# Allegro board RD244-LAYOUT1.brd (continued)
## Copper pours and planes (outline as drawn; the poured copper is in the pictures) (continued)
LGND on CONDUCTIVE3: 246.44,18.81 246.14,19.2 245.6,19.74 245.55,19.82 245.53,19.92 245.53,35.06 240.87,39.71 240.82,39.79 240.8,39.89 240.8,50.24 234.18,56.85 234.13,56.93 234.11,57.03 234.11,73.06 234.04,73.55 234.04,73.65 234.11,74.14 234.11,118.42 234.04,118.91 234.04,118.95 234.14,119.15 234.36,119.19 234.58,119.15 234.68,118.95 234.68,118.91 234.61,118.42 234.61,74.14 234.68,73.65 234.68,73.55 234.61,73.06 234.61,57.13 241.23,50.52 241.28,50.44 241.3,50.34 241.3,39.99 245.96,35.34 246.01,35.26 246.03,35.16 246.03,20.02 246.5,19.56 246.89,19.26 246.95,19.21 246.98,19.14 246.99,19.06 246.98,18.98 246.94,18.9 246.86,18.84 246.81,18.77 246.74,18.72 246.59,18.71 246.46,18.78
LGND on CONDUCTIVE3: 261.44,70.26 260.95,70.33 259.92,70.33 259.82,70.35 259.74,70.41 254.63,75.52 249.2,75.52 249.17,75.51 249.13,75.51 241.13,75.51 241.04,75.53 240.96,75.58 240.39,76.15 240.34,76.23 240.32,76.32 240.32,80.43 240.34,80.52 240.39,80.6 241.95,82.16 242.03,82.21 242.12,82.23 249.37,82.23 249.46,82.21 249.54,82.16 250.42,81.28 250.47,81.2 250.49,81.11 250.49,80.1 250.47,80.01 250.42,79.93 250.33,79.84 250.25,79.79 250.16,79.77 249.66,79.77 249.38,79.49 249.38,76.43 249.79,76.02 254.73,76.02 254.83,76 254.91,75.95 260.02,70.83 260.95,70.83 261.44,70.91 261.54,70.91 262.03,70.83 262.35,70.83 263.2,71.68 263.2,73.7 262.8,74.1 261.61,74.1 261.43,74.17 261.36,74.35 261.36,76.56 261.36,76.6 261.37,76.64 261.37,80.97 261.44,81.15 261.62,81.22 269.49,81.22 269.67,81.15 269.74,80.97 269.74,80.02 269.67,79.84 269.49,79.77 268.97,79.77 267.92,78.72 267.92,74.35 267.85,74.17 267.67,74.1 264.1,74.1 263.7,73.7 263.7,71.58 263.68,71.48 263.63,71.4 262.63,70.41 262.55,70.35 262.45,70.33 262.03,70.33 261.54,70.26
LGND on CONDUCTIVE3: 259.39,118.83 258.12,118.83 258.02,118.85 257.94,118.9 254.61,122.24 243.8,122.24 243.76,122.25 243.73,122.27 239.73,126.27 239.71,126.3 239.7,126.34 239.7,129.81 239.71,129.85 239.73,129.88 239.97,130.12 240,130.14 240.04,130.15 241.26,130.15 241.3,130.14 241.33,130.12 242.48,128.97 248.43,128.97 248.47,128.96 248.5,128.94 249.04,128.4 249.06,128.37 249.07,128.33 249.07,127.04 249.06,127 249.04,126.97 248.96,126.89 248.93,126.87 248.89,126.86 248.51,126.86 247.9,126.25 247.9,124.09 249.25,122.74 254.77,122.74 254.81,122.73 254.84,122.71 258.22,119.33 259.39,119.33 260.02,119.42 260.13,119.38 260.47,119.33 260.54,119.33 261.6,120.39 261.6,123.68 261.6,123.72 261.61,123.75 261.61,128.09 261.68,128.27 261.86,128.34 269.73,128.34 269.91,128.27 269.98,128.09 269.98,127.13 269.91,126.95 269.73,126.88 269.21,126.88 268.16,125.83 268.16,121.81 268.09,121.63 267.91,121.56 262.57,121.56 262.1,121.08 262.1,120.29 262.08,120.19 262.03,120.11 260.82,118.9 260.74,118.85 260.64,118.83 260.47,118.83 259.98,118.76
LGND on CONDUCTIVE4: outline of 150 points within 248.3,18.8 298.45,143.8 ; 25 cut-outs
LGND on CONDUCTIVE5: outline of 224 points within 235.06,1.55 298.45,143.8 ; 46 cut-outs
OUTA2 on TOP: 245.01,6.25 244.9,6.29 244.86,6.4 244.86,7.19 244.9,7.33 245.04,7.37 245.58,7.25 246.05,7.72 245.93,8.26 246.02,8.44 246.21,8.37 246.22,8.33 246.52,6.99 246.71,6.8 246.79,6.8 247.17,6.91 247.23,6.92 247.28,6.9 247.35,6.83 247.36,6.73 247.34,6.69 247.3,6.65 247.32,6.64 247.34,6.61 247.36,6.58 247.34,6.44 247.21,6.38 247.17,6.39 246.79,6.5 246.5,6.5 246.29,6.29 246.25,6.26 246.19,6.25
OUTA2 on BOTTOM: 247.15,6.47 247.14,6.57 247.16,6.61 247.2,6.65 247.18,6.66 247.16,6.69 247.14,6.72 247.16,6.86 247.29,6.92 247.33,6.91 247.71,6.8 251.71,6.8 254.29,9.38 254.34,9.41 254.4,9.43 258.54,9.43 258.84,9.47 258.88,9.47 259.64,9.47 259.84,9.28 259.64,9.07 258.88,9.07 258.84,9.08 258.54,9.12 254.46,9.12 251.88,6.54 251.83,6.51 251.78,6.5 247.71,6.5 247.33,6.39 247.27,6.38 247.22,6.4
OUTB2 on TOP: 251.34,5.63 251.45,6.01 251.45,7.49 251.11,7.83 250.91,7.83 249.97,7.22 249.77,7.26 249.81,7.47 250.28,7.77 250.28,8.43 249.81,8.73 249.77,8.94 249.97,8.98 251.13,8.23 251.74,7.61 251.75,7.55 251.75,6.01 251.86,5.63 251.87,5.56 251.84,5.5 251.76,5.44 251.65,5.45 251.62,5.47 251.6,5.5 251.59,5.48 251.56,5.46 251.53,5.44 251.39,5.46 251.33,5.59
OUTB2 on BOTTOM: 251.53,5.35 251.51,5.48 251.52,5.52 251.55,5.55 251.52,5.58 251.51,5.62 251.53,5.75 251.65,5.82 251.68,5.81 251.71,5.8 251.89,5.73 254.89,8.73 254.94,8.76 255,8.78 258.54,8.78 258.84,8.82 258.88,8.82 259.64,8.82 259.84,8.62 259.64,8.43 258.88,8.43 258.84,8.43 258.54,8.47 255.06,8.47 252.03,5.44 252.01,5.42 251.98,5.41 251.71,5.3 251.68,5.29 251.65,5.28
OUTD2 on TOP: 250.46,2.01 250.26,2.06 250.3,2.26 250.77,2.57 250.77,2.7 250.05,2.7 249.9,2.85 250.05,3 250.77,3 250.77,3.23 250.3,3.54 250.26,3.74 250.46,3.79 251.62,3.05 251.82,3.11 251.87,3.12 251.91,3.11 251.97,3.08 252.01,3.02 252.01,3 252.05,2.91 252.02,2.82 252,2.79 251.98,2.63 251.82,2.59 251.51,2.68
OUTD2 on BOTTOM: 244.57,1.48 244.35,1.7 244.57,1.93 244.75,1.93 244.8,1.92 245.13,1.85 250.69,1.85 251.47,2.63 251.66,2.98 251.83,3.05 251.94,2.91 251.94,2.89 251.96,2.89 252.1,2.78 252.03,2.61 251.68,2.42 250.86,1.59 250.81,1.56 250.75,1.55 245.13,1.55 244.8,1.48 244.75,1.48
OUTE on CONDUCTIVE4: 250.7,50.65 245.7,50.65 245.6,50.67 245.52,50.72 237.02,59.22 236.97,59.3 236.95,59.4 236.95,119.93 236.97,120.03 237.02,120.11 238.68,121.77 238.76,121.82 238.86,121.84 253.07,121.84 253.17,121.82 253.25,121.77 256.97,118.05 258.85,118.05 259.34,118.12 259.38,118.12 259.58,118.02 259.62,117.8 259.58,117.58 259.38,117.48 259.34,117.48 258.85,117.55 256.86,117.55 256.77,117.57 256.69,117.62 252.97,121.34 238.96,121.34 237.45,119.83 237.45,76.65 237.65,76.45 238.18,76.45 238.21,76.46 238.25,76.46 241.49,76.46 241.59,76.44 241.67,76.39 243.32,74.73 253.52,74.73 253.62,74.71 253.7,74.66 258.76,69.59 260.82,69.59 261.31,69.66 261.35,69.66 261.55,69.56 261.59,69.34 261.55,69.12 261.35,69.02 261.31,69.02 260.82,69.09 258.66,69.09 258.56,69.11 258.48,69.16 253.42,74.23 243.22,74.23 243.12,74.25 243.04,74.3 241.39,75.96 238.73,75.96 238.7,75.95 238.66,75.95 237.65,75.95 237.45,75.75 237.45,59.5 245.8,51.15 250.8,51.15 250.9,51.13 250.98,51.08 254.26,47.8 254.31,47.72 254.33,47.62 254.18,47.39 253.9,47.44
OUTF on TOP: 260.78,14.46 260.79,14.51 260.9,14.89 260.9,16.37 260.91,16.43 261.17,16.71 261.22,16.74 261.28,16.75 261.38,16.75 262.81,17.61 263.1,17.65 263.9,17.65 264.95,16.6 263.9,15.55 263.1,15.55 262.91,15.57 262.54,15.71 261.8,16.18 261.38,16.18 261.2,16 261.2,14.89 261.31,14.51 261.32,14.43 261.28,14.36 261.21,14.32 261.13,14.32 261.09,14.34 261.05,14.38 261.04,14.36 261.01,14.34 260.98,14.32 260.86,14.33 260.79,14.42
OUTF on BOTTOM: 259.75,120.08 259.69,120.09 259.65,120.12 259.61,120.16 259.58,120.2 259.57,120.26 259.57,120.57 259.58,120.63 259.61,120.67 259.8,120.86 259.85,120.89 259.91,120.91 261.49,120.91 261.9,120.49 261.49,120.08
OUTF on CONDUCTIVE3: 250.6,50.85 245.4,50.85 245.3,50.87 245.22,50.92 237.12,59.02 237.07,59.1 237.05,59.2 237.05,122.5 237.07,122.6 237.12,122.68 238.12,123.68 238.2,123.73 238.3,123.75 238.88,123.75 239.37,123.82 239.41,123.82 239.61,123.72 239.65,123.5 239.61,123.28 239.41,123.18 239.37,123.18 238.88,123.25 238.4,123.25 237.55,122.4 237.55,77.9 237.8,77.65 237.85,77.65 237.88,77.64 238.29,77.64 238.78,77.71 238.82,77.71 239.02,77.61 239.06,77.39 239.02,77.17 238.82,77.07 238.78,77.07 238.29,77.14 237.8,77.14 237.55,76.89 237.55,59.3 245.5,51.35 250.7,51.35 250.8,51.33 250.88,51.28 254.44,47.72 254.49,47.64 254.51,47.54 254.36,47.31 254.08,47.36
OUTF on CONDUCTIVE4: 261.3,71.7 260.81,71.77 258.3,71.77 258.2,71.79 258.12,71.84 254.57,75.4 244.22,75.4 244.12,75.42 244.04,75.47 242.38,77.14 239.37,77.14 238.88,77.07 238.84,77.07 238.64,77.17 238.6,77.39 238.64,77.61 238.84,77.71 238.88,77.71 239.37,77.64 242.48,77.64 242.58,77.62 242.66,77.57 244.32,75.9 254.67,75.9 254.77,75.88 254.85,75.83 258.4,72.27 260.81,72.27 261.3,72.34 261.34,72.34 261.54,72.24 261.58,72.02 261.54,71.8 261.34,71.7
PFC_OFF on BOTTOM: 119.07,11.75 118.96,11.79 118.92,11.9 118.92,12.05 118.96,12.16 119.07,12.2 119.78,12.2 120.31,12.73 120.35,12.76 120.41,12.78 121.44,12.78 121.74,12.82 121.78,12.82 122.47,12.82 122.67,12.62 122.47,12.43 121.78,12.43 121.74,12.43 121.44,12.47 121.05,12.47 120.69,12.12 120.36,11.79 120.32,11.76 120.26,11.75
PN on BOTTOM (solid shape): 186.3,32.27 186.57,32.47 186.8,32.23 186.8,32.18 186.66,31.48 188.48,29.66 189.18,29.8 189.47,29.6 189.27,29.3 185.97,28.68 185.75,28.75 185.68,28.97
PN on BOTTOM (solid shape): 117.65,124.25 118.12,124.58 118.59,124.25 119.17,122.67 119.12,122.21 118.71,122 118.42,122.09 118.24,122.32 118.21,122.39 118.03,122.39 118,122.32 117.36,122.03 117.06,122.67
PN on CONDUCTIVE3 (solid shape): 112.42,98.34 112.58,98.48 112.72,98.33 112.72,98.31 112.69,98.07 113.41,97.35 113.65,97.38 113.81,97.25 113.68,97.08 112.43,96.92 112.3,96.96 112.26,97.09
PN on TOP: 209.16,15.06 209.05,15.1 209.01,15.21 209.01,17.56 209.05,17.67 209.16,17.71 209.42,17.71 209.48,17.7 209.52,17.67 210.67,16.52 210.7,16.48 210.71,16.42 210.71,15.21 210.67,15.1 210.56,15.06
PN on TOP: 188.35,6.48 188.35,6.72 187.88,6.96 187.83,6.99 187.79,7.04 187.77,7.3 187.99,7.43 188.05,7.42 188.11,7.4 189.2,6.85 195.86,6.85 197.3,8.29 197.3,8.53 197.16,8.99 195.1,8.99 194.64,9.45 195.1,9.91 197.33,9.91 197.47,10.15 197.83,10.53 197.88,10.56 197.94,10.57 202.04,10.57 202.1,10.56 202.15,10.53 203.51,9.16 207.15,9.16 208.07,10.08 208.26,10.43 208.43,10.5 208.54,10.36 208.54,10.34 208.56,10.34 208.7,10.23 208.63,10.06 208.28,9.87 207.32,8.9 207.27,8.87 207.21,8.86 203.45,8.86 203.39,8.87 203.34,8.9 201.98,10.27 198,10.27 197.83,10.1 197.83,9.97 197.87,9.91 200.1,9.91 200.56,9.45 200.1,8.99 198.04,8.99 197.85,8.35 197.85,8.24 197.83,8.14 197.78,8.06 196.14,6.42 196.06,6.37 195.96,6.35 189.2,6.35 188.11,5.8 188.07,5.78 187.76,5.92 187.88,6.24
PN on TOP: 125.17,10.5 125.18,10.55 125.25,10.88 125.25,10.94 125.15,11.03 124.62,11.03 124.6,11.04 124.55,11.03 124.51,11.04 124.2,11.14 123.89,11.04 123.84,11.03 123.71,11.11 123.71,11.26 123.75,11.3 123.71,11.34 123.71,11.49 123.84,11.57 123.89,11.56 124.2,11.46 124.51,11.56 124.55,11.57 124.6,11.56 124.64,11.57 124.68,11.56 125.06,11.45 125.75,11.45 125.8,11.49 125.86,11.5 127.47,11.5 127.57,11.46 127.62,11.35 127.62,11.14 127.53,10.86 127.26,10.74 127.03,10.74 126.96,10.75 126.9,10.76 126.43,10.95 125.78,10.95 125.58,10.75 125.62,10.55 125.62,10.5 125.62,10.32 125.4,10.1 125.17,10.32
PN on TOP: 226.36,2.15 226.2,2.15 225.9,2.1 225.87,2.1 225.7,2.1 225.5,2.3 225.7,2.5 225.87,2.5 225.9,2.5 226.14,2.46 226.33,2.46 226.68,2.57 227.02,2.75 227.07,2.77 227.1,2.77 227.49,2.77 227.81,2.84 227.9,2.85 228.12,2.62 227.9,2.4 227.81,2.41 227.49,2.48 227.19,2.48 227.03,2.18 226.98,2.12 226.9,2.1 226.88,2.1 226.86,2.08 226.84,2.07 226.78,2.04 226.71,2.05
PN on TOP: 215.67,2.54 215.56,2.58 215.52,2.69 215.52,5.04 215.53,5.1 215.77,5.36 215.82,5.39 215.88,5.4 218.72,5.4 219.05,5.47 219.1,5.47 219.28,5.47 219.5,5.25 219.28,5.03 219.1,5.03 219.05,5.03 218.72,5.1 215.94,5.1 215.82,4.98 215.82,3.88 215.95,3.75 217.69,3.75 217.75,3.74 217.79,3.71 217.95,3.55 219.15,3.55 219.26,3.51 219.3,3.4 219.3,3.3 219.26,3.19 219.15,3.15 216.59,3.15 216.02,2.58 215.98,2.55 215.92,2.54
PN on TOP: 199.31,2.85 199.25,2.86 199.21,2.89 198.84,3.26 198.81,3.3 198.8,3.36 198.8,7.95 198.84,8.06 198.95,8.1 206.85,8.1 206.96,8.06 207,7.95 207,4.86 206.99,4.8 206.96,4.76 205.09,2.89 205.05,2.86 204.99,2.85
PN on TOP: 100.19,1.51 100.13,1.52 100.09,1.55 99.77,1.87 99.74,1.91 99.73,1.97 99.73,2.75 99.74,2.81 99.77,2.85 100.07,3.15 100.11,3.18 100.17,3.19 101.31,3.19 101.37,3.18 101.41,3.15 101.51,3.05 102.7,3.05 102.76,3.04 102.8,3.01 103.41,2.4 108.59,2.4 108.65,2.39 108.69,2.36 108.9,2.15 109.32,2.15 109.33,2.17 109.35,2.19 109.5,2.35 109.5,3.12 109.7,3.33 109.9,3.12 109.9,2.38 109.89,2.32 109.86,2.27 109.75,2.16 109.75,1.7 109.71,1.59 109.6,1.55 108.26,1.55 108.2,1.56 108.16,1.59 107.8,1.95 103.03,1.95 102.63,1.55 102.59,1.52 102.53,1.51
PN on TOP, BOTTOM: 189.13,144.72 189.07,144.73 189.03,144.76 188.48,145.31 188.45,145.35 188.44,145.41 188.44,146.86 188.45,146.92 188.48,146.96 188.84,147.32 188.88,147.35 188.94,147.36 190.11,147.36 190.17,147.35 190.21,147.32 190.57,146.96 190.6,146.92 190.61,146.86 190.61,145.18 190.6,145.12 190.57,145.08 190.25,144.76 190.21,144.73 190.15,144.72
PN on BOTTOM: 122.14,121.08 122.03,121.12 121.99,121.23 121.99,143.68 122.03,143.79 122.14,143.83 138.83,143.83 138.94,143.79 138.98,143.68 138.98,121.23 138.94,121.12 138.83,121.08
PN on BOTTOM: 120.06,24.6 120,24.61 119.96,24.64 119.14,25.46 119.11,25.5 119.1,25.56 119.1,29.34 119.11,29.4 119.14,29.44 119.96,30.26 120,30.29 120.06,30.3 124.04,30.3 124.1,30.29 124.14,30.26 124.96,29.44 124.99,29.4 125,29.34 125,25.56 124.99,25.5 124.96,25.46 124.14,24.64 124.1,24.61 124.04,24.6
PN on BOTTOM: 118.17,5.08 118.18,5.13 118.25,5.45 118.18,5.77 118.17,5.82 118.17,6.18 118.18,6.21 118.18,6.4 118.13,6.45 118.06,6.45 117.68,6.34 117.61,6.33 117.55,6.36 117.5,6.41 117.49,6.48 117.5,6.55 117.55,6.6 117.51,6.63 117.49,6.67 117.49,6.76 117.56,6.85 117.68,6.86 118.06,6.75 118.11,6.75 118.17,6.81 118.17,7.28 118.18,7.33 118.25,7.65 118.18,7.97 118.17,8.02 118.17,8.2 118.4,8.43 118.62,8.2 118.62,8.02 118.62,7.97 118.55,7.65 118.62,7.33 118.62,7.28 118.62,6.92 118.55,6.58 118.55,6.55 118.62,6.23 118.62,6.18 118.62,5.82 118.62,5.77 118.55,5.45 118.62,5.13 118.62,5.08 118.62,4.9 118.4,4.67 118.17,4.9
PN on BOTTOM: 122.23,99.96 122.17,99.97 122.13,100 120.05,102.08 120.02,102.12 120.01,102.18 120.01,104.48 120.02,104.54 120.05,104.58 121.45,105.98 121.49,106.01 121.55,106.02 137.15,106.02 137.21,106.01 137.25,105.98 138.95,104.28 138.98,104.24 138.99,104.18 138.99,101.92 138.98,101.86 138.95,101.82 137.13,100 137.09,99.97 137.03,99.96
PN on BOTTOM: 118.11,10.9 118.05,10.91 118.01,10.94 117.95,11 113.16,11 113.1,11.01 113.06,11.04 112.94,11.16 112.91,11.2 112.9,11.26 112.9,13.34 112.91,13.4 112.94,13.44 113.16,13.66 113.2,13.69 113.26,13.7 114.94,13.7 115,13.69 115.04,13.66 115.16,13.54 115.19,13.5 115.2,13.44 115.2,12.2 115.4,12 117.94,12 118,11.99 118.04,11.96 118.65,11.35 120.44,11.35 120.57,11.48 120.62,11.51 120.68,11.53 123.62,11.53 123.66,11.56 123.7,11.59 123.76,11.6 124.75,11.6 124.86,11.56 124.9,11.45 124.9,11.16 124.89,11.1 124.86,11.06 124.84,11.04 124.8,11.01 124.74,11 123.66,11 123.6,11.01 123.56,11.04 123.48,11.12 123.45,11.14 123.43,11.17 123.18,11.13 123.15,11.12 121.91,11.12 121.88,11.13 121.58,11.18 121.48,11.18 121.42,11.13 121.36,11.12 121.27,11.12 121.09,10.94 121.05,10.91 120.99,10.9
PN on BOTTOM: 124.95,4.55 124.84,4.59 124.8,4.7 124.8,6.1 124.84,6.21 124.95,6.25 127.6,6.25 127.71,6.21 127.75,6.1 127.75,4.7 127.71,4.59 127.6,4.55
PN on BOTTOM: 187.36,28.66 187.3,28.67 187.26,28.7 186.03,29.93 186,29.97 185.99,30.03 185.99,33.32 186,33.38 186.03,33.42 187.05,34.44 187.09,34.47 187.15,34.48 190.43,34.48 190.49,34.47 190.53,34.44 191.55,33.42 191.58,33.38 191.59,33.32 191.59,29.76 191.58,29.7 191.55,29.66 190.59,28.7 190.55,28.67 190.49,28.66
PN on BOTTOM: 154.02,10.7 153.97,10.71 153.92,10.74 153.11,11.56 153.07,11.6 153.06,11.66 153.06,15.44 153.07,15.5 153.11,15.54 153.92,16.36 153.97,16.39 154.02,16.4 158,16.4 158.06,16.39 158.11,16.36 158.92,15.54 158.95,15.5 158.96,15.44 158.96,11.66 158.95,11.6 158.92,11.56 158.11,10.74 158.06,10.71 158,10.7
PN on BOTTOM: 207.72,9.28 207.5,9.5 207.72,9.72 207.89,9.72 207.94,9.72 208.2,9.66 208.35,9.81 208.35,9.84 208.24,10.22 208.24,10.32 208.3,10.39 208.34,10.41 208.39,10.41 208.39,10.42 208.45,10.54 208.58,10.56 208.96,10.45 210.84,10.45 210.95,10.48 210.95,11.3 210.99,11.41 211.1,11.45 212.54,11.45 212.6,11.44 212.64,11.41 212.75,11.3 214.5,11.3 214.7,11.5 214.7,12.65 214.74,12.76 214.85,12.8 217.35,12.8 217.46,12.76 217.5,12.65 217.5,12.5 217.46,12.39 217.35,12.35 215.6,12.35 215.2,11.95 215.2,11.36 215.19,11.3 215.16,11.26 214.79,10.89 214.75,10.86 214.69,10.85 213.05,10.85 212.55,10.35 212.55,10 212.51,9.89 212.4,9.85 211.21,9.85 211.15,9.86 211.11,9.89 211,10 210.84,10.04 208.71,10.04 208.65,9.84 208.65,9.75 208.64,9.69 208.36,9.39 208.32,9.37 208.28,9.35 207.94,9.28 207.89,9.28
PN on BOTTOM: 101.71,18.86 101.23,19.42 100.22,19.97 99.15,18.9 99.15,17.35 98.9,17.1 98.65,17.35 98.65,19 98.67,19.1 98.72,19.18 99.97,20.43 100.05,20.48 100.15,20.5 101.4,21.17 101.73,21.08 101.66,20.75 101.64,20.73 101.1,20.44 101.1,20.06 101.25,19.97 101.38,19.96 101.48,19.89 101.55,19.81 101.64,19.77 101.66,19.75 101.74,19.67 101.77,19.56 101.85,19.46 101.95,19.46 102.32,19.89 102.66,19.93 102.71,19.59 102.7,19.56 102.44,19.26 102.44,18.84 104.18,17.1 104.18,16.75 103.82,16.75
PN on BOTTOM: 187.16,5.47 187.1,5.48 187.06,5.51 186.64,5.93 186.61,5.97 186.6,6.03 186.6,7.08 186.61,7.14 186.64,7.18 187.15,7.69 187.19,7.72 187.25,7.73 188.15,7.73 188.21,7.72 188.25,7.69 188.71,7.23 188.74,7.19 188.75,7.13 188.75,6.03 188.74,5.97 188.71,5.93 188.29,5.51 188.25,5.48 188.19,5.47
PN on BOTTOM: 200.55,1.82 200.49,1.83 200.45,1.86 199.26,3.05 199.23,3.09 199.22,3.15 199.22,3.31 199.23,3.37 199.26,3.41 199.29,3.44 199.33,3.47 199.39,3.48 199.57,3.48 199.63,3.47 199.67,3.44 200.76,2.35 200.79,2.31 200.8,2.25 200.8,1.97 200.76,1.86 200.65,1.82
PN on BOTTOM: 218.1,5.38 218.11,5.43 218.18,5.75 218.18,6.04 218.13,6.34 218.12,6.38 218.12,6.88 218.02,6.98 217.97,7.12 217.97,7.83 217.98,7.87 217.99,7.91 218.1,8.29 218.1,10.09 218.06,10.22 218.06,10.26 218.06,10.3 218.06,10.34 218.06,10.38 218.17,10.75 218.11,11.06 218.1,11.11 218.1,11.2 218.32,11.43 218.55,11.2 218.55,11.11 218.54,11.06 218.48,10.75 218.59,10.38 218.59,10.34 218.59,10.3 218.59,10.26 218.59,10.22 218.47,9.84 218.47,8.04 218.51,7.91 218.52,7.87 218.53,7.83 218.53,6.38 218.52,6.34 218.47,6.04 218.47,5.75 218.54,5.43 218.55,5.38 218.55,5.2 218.32,4.97 218.1,5.2
PN on BOTTOM: 119.09,100.5 117.77,101.82 117.66,101.99 117.62,102.18 117.62,120.39 117.06,121.89 117.06,121.9 117.37,122.53 118,122.24 118.12,121.92 118.24,122.24 118.87,122.53 119.18,121.9 119.17,121.89 118.62,120.39 118.62,102.39 119.94,101.06 120.05,100.9 120.09,100.71 120.09,93.54 119.59,93.04 119.09,93.54
PN on BOTTOM: 71.71,130.1 71.65,130.11 71.61,130.14 71.09,130.66 71.06,130.7 71.05,130.76 71.05,133.24 71.06,133.3 71.09,133.34 71.61,133.86 71.65,133.89 71.71,133.9 74.29,133.9 74.35,133.89 74.39,133.86 74.91,133.34 74.94,133.3 74.95,133.24 74.95,130.56 74.94,130.5 74.91,130.46 74.59,130.14 74.55,130.11 74.49,130.1
PN on CONDUCTIVE2, CONDUCTIVE5: outline of 271 points within 70.95,0.8 229.5,148.28 ; 18 cut-outs
PN on CONDUCTIVE2, CONDUCTIVE5: 116.13,3.77 116.11,3.8 116.1,3.84 116.1,17.72 116.11,17.76 116.13,17.79 119.19,20.85 119.22,20.87 119.26,20.88 130.4,20.88 130.44,20.87 130.47,20.85 133.57,17.75 133.59,17.72 133.6,17.68 133.6,9.12 133.56,9.04 133.48,9.02 132.63,8.34 133.48,7.66 133.56,7.64 133.6,7.56 133.6,4.44 133.59,4.4 133.57,4.37 131.83,2.63 131.8,2.61 131.76,2.6 117.34,2.6 117.3,2.61 117.27,2.63 ; 4 cut-outs
PN on CONDUCTIVE4: 113.28,12.9 113.24,12.91 113.21,12.93 113.09,13.05 113.07,13.08 113.06,13.12 113.06,13.65 113.07,13.69 113.09,13.72 114.55,15.18 114.58,15.2 114.62,15.21 115,15.21 115.07,15.18 115.1,15.11 115.1,13.44 114.97,13.06 114.6,12.9
PN on CONDUCTIVE4: 155.55,3.27 155.36,3.31 155.2,3.42 145.95,12.67 145.84,12.83 145.8,13.02 145.8,18.86 141.11,23.55 120.08,23.55 119.89,23.59 119.73,23.7 117.51,25.92 117.4,26.08 117.36,26.27 117.36,92.61 117.4,92.8 117.51,92.96 119.24,94.69 119.78,94.8 120.09,94.34 120.09,93.54 119.94,93.19 119.59,93.04 119,93.04 118.36,92.4 118.36,26.48 120.29,24.55 141.32,24.55 141.51,24.51 141.67,24.4 146.65,19.42 146.76,19.26 146.8,19.07 146.8,13.23 155.76,4.27 191.91,4.27 194.2,6.55 194.36,6.66 194.55,6.7 198.49,6.7 199.15,7.35 199.69,7.46 200,7 200,6.2 199.85,5.85 199.5,5.7 194.76,5.7 192.47,3.42 192.31,3.31 192.12,3.27
SIG1 on CONDUCTIVE3 (solid shape): 24.73,71.29 25.07,71.21 24.99,70.86 24.67,70.67 24.67,69.37 24.99,69.18 25.07,68.83 24.73,68.75 22.99,69.81 22.87,70.02 22.99,70.23
SIG1 on TOP: 9.56,30.46 9.5,30.48 9.46,30.51 1.4,38.56 0.86,39.37 0.67,40.33 0.67,63.89 0.86,64.85 1.4,65.66 16.27,80.53 16.27,88.5 16.28,88.55 16.32,88.6 24.42,96.71 24.47,96.74 24.53,96.75 45.72,96.75 45.78,96.74 45.83,96.71 47.77,94.77 47.83,94.71 47.86,94.66 47.87,94.6 47.87,91.59 47.86,91.54 47.82,91.49 47.38,91.04 47.33,91.01 47.27,91 44.53,91 44.47,91.01 44.42,91.04 43.71,91.75 26.54,91.75 21.46,86.67 21.46,78.71 21.45,78.65 21.42,78.6 5.67,62.85 5.67,50.13 6,49.8 6.59,49.8 9.06,52.28 9.44,54.29 9.46,54.34 9.48,54.36 9.5,54.39 9.66,54.4 9.74,54.26 9.73,54.23 9.6,53.5 10.5,52.6 11.23,52.73 11.26,52.74 11.4,52.66 11.39,52.5 11.36,52.48 11.34,52.46 11.29,52.44 9.28,52.06 5.67,48.46 5.67,41.37 12.89,34.14 12.92,34.1 12.94,34.04 12.94,32.06 12.92,32 12.89,31.96 11.44,30.51 11.4,30.48 11.34,30.46
SIG1 on TOP, CONDUCTIVE2, CONDUCTIVE5: 23.51,60.6 23.45,60.61 23.41,60.64 22.34,61.71 22.31,61.75 22.3,61.81 22.3,69.89 22.31,69.95 22.34,69.99 24.15,71.8 24.15,82.24 24.16,82.3 24.19,82.34 30.81,88.96 30.85,88.99 30.91,89 41.94,89 42,88.99 42.04,88.96 43.2,87.8 54.63,87.8 57.7,90.87 57.7,93.84 57.71,93.9 57.74,93.94 59.11,95.31 59.15,95.34 59.21,95.35 61.78,95.35 61.84,95.34 61.88,95.31 63.01,94.18 63.04,94.14 63.05,94.08 63.05,88.56 63.04,88.5 63.01,88.46 57.09,82.54 57.05,82.51 56.99,82.5 40.86,82.5 40.8,82.51 40.76,82.54 39.6,83.7 33.2,83.7 29.84,80.34 29.84,61.86 29.83,61.8 29.8,61.76 28.68,60.64 28.64,60.61 28.58,60.6
SIG1 on BOTTOM: 27.61,53.12 27.36,53.37 27.61,53.62 30.45,53.62 30.75,53.91 30.75,54.2 30.7,54.21 30.07,54.39 27.61,54.39 27.36,54.64 27.61,54.89 30.07,54.89 30.76,55.08 30.82,55.09 32,55.09 32.43,54.75 32.22,54.25 31.65,53.93 30.9,53.19 30.82,53.13 30.73,53.12
SIG1 on BOTTOM: 18,52.91 17.57,53.25 17.78,53.75 18.35,54.07 19.1,54.81 19.18,54.87 19.27,54.88 22.39,54.88 22.64,54.63 22.39,54.38 19.38,54.38 19.15,54.16 19.15,53.94 19.3,53.79 19.93,53.61 22.39,53.61 22.64,53.36 22.39,53.11 19.93,53.11 19.24,52.92 19.18,52.91
SIG1 on BOTTOM: 3.17,47.55 1.4,48.28 0.67,50.05 0.67,63.89 0.86,64.85 1.4,65.66 16.46,80.72 16.46,87.71 16.65,88.67 17.19,89.48 23.73,96.02 27.27,96.02 27.27,92.48 21.46,86.67 21.46,79.68 21.27,78.72 20.73,77.91 5.67,62.85 5.67,52.12 5.67,52.11 8.34,50.3 13.75,50.3 14.26,50.81 14.34,50.87 14.44,50.89 16.07,50.89 16.76,51.08 16.82,51.09 18,51.09 18.45,50.64 18,50.19 16.82,50.19 16.76,50.19 16.7,50.21 16.07,50.39 14.54,50.39 14.03,49.87 13.95,49.82 13.85,49.8 8.34,49.8 5.67,47.99 5,47.66 4.26,47.55
SIG1 on BOTTOM: 31.55,57.69 31.56,57.75 31.75,58.44 31.75,58.64 29.79,60.6 23.51,60.6 23.45,60.61 23.41,60.64 22.34,61.71 22.31,61.75 22.3,61.81 22.3,69.89 22.31,69.95 22.34,69.99 24.15,71.8 24.15,82.24 24.16,82.3 24.19,82.34 30.81,88.96 30.85,88.99 30.91,89 41.94,89 42,88.99 42.04,88.96 43.2,87.8 54.63,87.8 57.7,90.87 57.7,93.84 57.71,93.9 57.74,93.94 59.11,95.31 59.15,95.34 59.21,95.35 61.78,95.35 61.84,95.34 61.88,95.31 63.01,94.18 63.04,94.14 63.05,94.08 63.05,88.56 63.04,88.5 63.01,88.46 57.09,82.54 57.05,82.51 56.99,82.5 40.86,82.5 40.8,82.51 40.76,82.54 39.6,83.7 33.2,83.7 29.84,80.34 29.84,61.25 32.18,58.92 32.23,58.84 32.25,58.74 32.25,58.44 32.44,57.75 32.45,57.69 32.45,57.36 32,56.91 31.55,57.36
SIG1 on CONDUCTIVE2, CONDUCTIVE5: 9.56,30.46 9.5,30.48 9.46,30.51 1.4,38.56 0.86,39.37 0.67,40.33 0.67,63.89 0.86,64.85 1.4,65.66 16.27,80.53 16.27,88.5 16.28,88.55 16.32,88.6 24.42,96.71 24.47,96.74 24.53,96.75 45.72,96.75 45.78,96.74 45.83,96.71 47.83,94.71 47.86,94.66 47.87,94.6 47.87,91.59 47.86,91.54 47.82,91.49 47.38,91.04 47.33,91.01 47.27,91 44.53,91 44.47,91.01 44.42,91.04 43.71,91.75 26.54,91.75 21.46,86.67 21.46,78.71 21.45,78.65 21.42,78.6 5.67,62.85 5.67,41.37 12.89,34.14 12.92,34.1 12.94,34.04 12.94,32.06 12.92,32 12.89,31.96 11.44,30.51 11.4,30.48 11.34,30.46
SIG0012 on BOTTOM: 100.16,12.5 99.9,12.5 99.8,12.52 99.72,12.57 98.72,13.57 98.67,13.65 98.65,13.75 98.65,15.25 98.9,15.5 99.15,15.25 99.15,13.85 100,13 100.16,13 101.4,13.67 101.45,13.69 101.51,13.7 101.55,13.73 101.6,13.76 102.96,14.16 103.75,14.95 103.75,15.9 103.79,16.01 103.9,16.05 104.09,16.05 104.15,16.04 104.19,16.01 104.45,15.75 106.47,15.75 106.72,15.5 106.47,15.25 104.75,15.25 103.31,13.81 102.91,12.45 102.9,12.44 102.59,12.28 102.43,12.59 102.6,13.18 102.33,13.45 101.74,13.28 101.69,13.27 101.64,13.23 101.1,12.94 101.1,12.56 101.64,12.27 101.66,12.25 101.73,11.92 101.4,11.83
SIG0013 on TOP: 165.47,81.78 165.41,81.79 165.37,81.82 164.39,82.8 164.36,82.84 164.35,82.9 164.35,83.89 158.44,89.8 156.32,89.8 156.26,89.81 156.22,89.84 154.06,92 154.03,92.05 154.01,92.11 154.01,104.85 154.03,104.91 154.06,104.96 154.66,105.56 154.7,105.59 154.76,105.6 163.04,105.6 163.1,105.59 163.14,105.56 163.96,104.74 163.99,104.7 164,104.64 164,97.66 169.08,92.58 169.11,92.54 169.12,92.48 169.12,83.19 169.11,83.13 169.08,83.09 167.81,81.82 167.77,81.79 167.71,81.78
SIG0013 on TOP: 67.29,8.94 67.08,9.27 67,9.65 67,17.5 68,18.5 69,17.5 69,10.06 70.57,8.49 79.67,8.49 80.8,9.62 80.8,23.57 80.81,23.63 80.84,23.67 88.01,30.84 88.01,34.76 78.86,43.91 78.78,43.95 78.16,43.95 78.1,43.96 78.06,43.99 77.44,44.61 77.41,44.65 77.4,44.71 77.4,49.44 77.41,49.5 77.44,49.54 78.16,50.26 78.2,50.29 78.26,50.3 81.94,50.3 82,50.29 82.04,50.26 82.32,49.98 82.35,49.93 82.37,49.87 82.37,47.47 82.37,47.47 94.06,35.78 99.46,35.78 99.52,35.77 99.56,35.74 100.61,34.69 100.64,34.65 100.65,34.59 100.65,32.17 100.64,32.11 100.61,32.07 99.27,30.73 99.23,30.7 99.17,30.69 94.93,30.69 86.12,21.88 86.12,11.98 86.11,11.92 86.08,11.88 85.58,11.38 85.54,11.35 85.48,11.34 83.5,11.34 82.9,10.74 82.9,9.31 82.82,8.93 82.61,8.6 80.79,6.78 80.46,6.57 80.08,6.49 70.16,6.49 69.78,6.57 69.45,6.78
SIG0013 on TOP, BOTTOM: 74.47,11.02 74.09,11.1 73.77,11.31 73.03,12.05 72.82,12.37 72.74,12.75 72.74,18.36 67.42,23.68 58.59,23.68 55.8,20.88 55.47,20.67 55.09,20.59 42,20.59 38.21,16.79 38.03,16.65 37.82,16.55 36.92,16.69 36.5,17.5 36.52,17.7 36.58,17.88 36.67,18.06 36.79,18.21 40.88,22.3 41.21,22.51 41.59,22.59 54.68,22.59 58.16,26.07 58.71,27.08 58.71,27.64 58.79,28.02 59.01,28.35 59.75,29.09 60.07,29.3 60.45,29.38 69.43,29.38 69.81,29.3 70.13,29.09 77.57,21.65 77.78,21.33 77.86,20.95 77.86,12.17 77.78,11.79 77.57,11.47 77.41,11.31 77.09,11.1 76.71,11.02
SIG0013 on TOP, BOTTOM: 122.26,80.5 122.2,80.51 122.16,80.54 120.74,81.96 120.71,82 120.7,82.06 120.7,87.84 120.71,87.9 120.74,87.94 122.36,89.56 122.4,89.59 122.46,89.6 130.9,89.6 141.5,100.2 141.5,104.04 141.51,104.1 141.54,104.14 142.96,105.56 143,105.59 143.06,105.6 150.74,105.6 150.8,105.59 150.84,105.56 151.46,104.94 151.49,104.9 151.5,104.84 151.5,100.76 151.49,100.7 151.46,100.66 131.34,80.54 131.3,80.51 131.24,80.5
SIG0013 on BOTTOM: 44.59,25.56 44.53,25.57 44.49,25.6 43.81,26.28 43.77,26.33 43.76,26.39 43.76,28.58 43.77,28.61 43.78,28.65 43.98,28.97 55.08,40.12 55.89,40.66 56.85,40.85 72.87,40.85 72.93,40.84 72.98,40.81 75.39,38.39 80.63,38.39 86.19,43.95 86.19,57.91 86.2,57.97 86.23,58.01 103.26,75.04 103.26,78.85 95.4,86.71 95.22,86.9 94.92,87.33 94.7,87.8 94.57,88.31 94.52,88.83 94.52,111.56 84.08,122 72.34,122 72.28,122.01 72.24,122.04 71.1,123.18 71.09,123.2 71.07,123.23 71.06,123.26 71.05,123.3 71.05,125.78 71.05,125.81 71.06,125.83 71.06,126.27 71.07,126.33 71.1,126.37 72.19,127.46 72.23,127.49 72.29,127.5 85.82,127.5 86.97,127.27 87.95,126.62 99.64,114.93 100.29,113.95 100.52,112.8 100.52,90.07 108.38,82.21 109.03,81.24 109.26,80.09 109.26,73.81 109.04,72.66 108.38,71.68 92.19,55.49 92.19,42.71 91.96,41.56 91.31,40.59 81.27,30.54 81.22,30.51 81.16,30.5 76.28,30.5 76.22,30.51 76.17,30.54 70.86,35.85 57.89,35.85 47.69,25.66 47.62,25.59 47.57,25.57 47.52,25.56
SIG0013 on BOTTOM: outline of 101 points within 67,6.49 160.2,70.66
SIG0013 on BOTTOM: 94.89,3.1 94.29,3.7 94.89,4.3 95.21,4.3 95.36,4.28 95.49,4.23 95.75,4.1 98.35,4.1 98.61,4.23 98.74,4.28 98.89,4.3 99.21,4.3 99.81,3.7 99.21,3.1 98.89,3.1 98.74,3.12 98.61,3.17 97.89,3.55 96.21,3.55 95.49,3.17 95.36,3.12 95.21,3.1
SIG0013 on BOTTOM: 77.95,44.27 77.89,44.28 77.85,44.31 77.01,45.15 76.98,45.19 76.97,45.25 76.97,66.25 77.2,67.4 77.85,68.37 84.52,75.04 84.52,107.04 77.56,114 72.83,114 72.77,114.01 72.73,114.04 71.08,115.69 71.05,115.73 71.04,115.79 71.04,118.27 71.05,118.33 71.08,118.37 72.17,119.46 72.21,119.49 72.27,119.5 79.3,119.5 79.56,119.49 80.08,119.4 80.57,119.22 81.02,118.96 81.42,118.62 89.64,110.4 89.82,110.21 90.12,109.78 90.34,109.31 90.47,108.8 90.52,108.28 90.52,73.8 90.29,72.65 89.64,71.68 82.97,65.01 82.97,45.26 82.96,45.2 82.93,45.16 82.08,44.31 82.04,44.28 81.98,44.27
SIG0013 on CONDUCTIVE2, CONDUCTIVE5: 74.47,11.02 74.09,11.1 73.77,11.31 73.03,12.05 72.82,12.37 72.74,12.75 72.74,18.36 67.42,23.68 60.5,23.68 60.12,23.75 59.8,23.97 59.01,24.76 58.79,25.08 58.71,25.47 58.71,27.64 58.79,28.02 59.01,28.35 59.75,29.09 60.07,29.3 60.45,29.38 69.43,29.38 69.81,29.3 70.13,29.09 77.57,21.65 77.78,21.33 77.86,20.95 77.86,12.17 77.78,11.79 77.57,11.47 77.41,11.31 77.09,11.1 76.71,11.02
SIG0013 on CONDUCTIVE2, CONDUCTIVE5: 81.61,11.34 81.57,11.35 81.54,11.37 80.83,12.08 80.81,12.11 80.8,12.15 80.8,23.57 80.81,23.63 80.84,23.67 88.01,30.84 88.01,34.76 78.86,43.91 78.78,43.95 78.16,43.95 78.1,43.96 78.06,43.99 77.44,44.61 77.41,44.65 77.4,44.71 77.4,49.44 77.41,49.5 77.44,49.54 78.16,50.26 78.2,50.29 78.26,50.3 81.94,50.3 82,50.29 82.04,50.26 82.32,49.98 82.35,49.93 82.37,49.87 82.37,47.47 82.37,47.47 94.06,35.78 99.46,35.78 99.52,35.77 99.56,35.74 100.61,34.69 100.64,34.65 100.65,34.59 100.65,32.17 100.64,32.11 100.61,32.07 99.27,30.73 99.23,30.7 99.17,30.69 94.93,30.69 86.12,21.88 86.12,11.98 86.11,11.92 86.08,11.88 85.58,11.38 85.54,11.35 85.48,11.34
SIG45 on BOTTOM: 120.29,7.86 120.27,8 120.28,8.03 120.27,8.05 120.29,8.19 120.42,8.25 120.45,8.25 120.78,8.18 120.81,8.18 121.47,8.83 121.51,8.86 121.55,8.87 121.9,8.93 122.47,8.93 122.67,8.72 122.47,8.53 121.89,8.53 121.86,8.53 121.63,8.56 120.98,7.92 120.94,7.89 120.91,7.88 120.88,7.88 120.78,7.88 120.45,7.8 120.42,7.8
SIG47 on TOP: 128.2,9.73 128.21,9.81 128.39,10.26 128.39,10.27 128.2,10.74 128.19,10.8 128.18,10.87 128.18,11.1 128.19,11.17 128.2,11.23 128.39,11.7 128.39,11.95 127.89,12.45 127.26,12.45 126.88,12.34 126.82,12.33 126.77,12.35 126.7,12.42 126.69,12.52 126.71,12.56 126.75,12.6 126.73,12.61 126.71,12.64 126.69,12.67 126.71,12.81 126.84,12.87 126.88,12.86 127.26,12.75 127.95,12.75 128.01,12.74 128.68,12.07 128.69,12.01 128.69,11.7 128.88,11.23 128.89,11.17 128.9,11.1 128.9,10.87 128.89,10.8 128.88,10.74 128.75,10.42 128.75,10.41 128.99,9.81 129,9.73 129,9.43 128.6,9.03 128.2,9.43
SIG0052 on BOTTOM: 243.76,127.97 243.65,128.01 243.61,128.12 243.61,128.99 243.09,129.51 242.54,129.51 242.43,129.55 242.39,129.66 242.39,130.06 242.4,130.12 242.43,130.16 243.27,131 243.31,131.03 243.37,131.04 247.03,131.04 247.14,131 247.18,130.89 247.18,129.85 247.44,129.59 247.47,129.55 247.48,129.49 247.48,128.12 247.44,128.01 247.33,127.97
SIG0053 on BOTTOM: 263.14,127.16 262.82,127.05 262.68,127.36 262.83,127.77 262.77,127.83 262.36,127.68 262.04,127.84 262.19,128.15 263.16,128.51 263.45,128.8 263.45,129.34 263.46,129.4 263.49,129.44 263.8,129.75 263.8,130.69 263.81,130.75 263.84,130.79 264.06,131.01 264.1,131.04 264.16,131.05 265.4,131.05 265.51,131.01 265.55,130.9 265.55,129.7 265.86,129.39 265.89,129.35 265.9,129.29 265.9,128.8 266.38,128.32 267.13,128.32 267.24,128.28 267.28,128.17 267.28,127.61 267.24,127.5 267.13,127.46 263.44,127.46
SIG0054 on BOTTOM: 262.26,79.4 262.2,79.41 262.16,79.44 262.04,79.56 262.01,79.6 262,79.66 262,80.04 262.01,80.1 262.04,80.14 262.56,80.66 262.6,80.69 262.66,80.7 263.3,80.7 263.85,81.25 263.85,83.7 263.89,83.81 264,83.85 265.02,83.85 265.13,83.81 265.17,83.7 265.17,81.38 266.05,80.5 267.15,80.5 267.26,80.46 267.3,80.35 267.3,79.85 267.26,79.74 267.15,79.7 263.8,79.7 263.54,79.44 263.5,79.41 263.44,79.4
SIG86 on BOTTOM: 113.9,8.01 113.76,8.02 112.9,8.46 112.46,8.46 112.23,8.41 112.18,8.4 112,8.4 111.78,8.62 112,8.85 112.18,8.85 112.23,8.84 112.55,8.78 112.94,8.78 113.76,9.19 113.9,9.21 114.22,9.21 114.36,9.19 114.5,9.14 114.76,9 115.07,9 115.75,9.3 115.84,9.31 116.89,9.31 116.99,9.3 117.66,9 117.74,9 119.12,10.38 119.17,10.41 119.22,10.43 120.25,10.43 120.57,10.49 120.62,10.5 120.73,10.5 121.14,10.5 121.42,10.78 121.45,10.81 121.5,10.82 121.74,10.87 121.78,10.88 122.47,10.88 122.67,10.68 122.47,10.47 121.54,10.47 121.16,10.09 121.11,10.06 121.05,10.05 120.62,10.05 120.57,10.06 120.25,10.12 119.29,10.12 117.91,8.74 117.86,8.71 117.8,8.7 117.66,8.7 116.99,8.4 116.89,8.39 115.84,8.39 115.75,8.4 115.6,8.46 115.22,8.46 114.5,8.08 114.36,8.02 114.22,8.01
SIG115 on TOP: 246.25,88.38 246.19,88.39 246.15,88.42 244.27,90.3 244.24,90.34 244.23,90.4 244.23,95.13 244.24,95.19 244.27,95.23 245.15,96.11 245.19,96.14 245.25,96.15 247.69,96.15 253.89,102.35 253.93,102.38 253.99,102.39 258.38,102.39 258.44,102.38 258.48,102.35 260.96,99.87 260.99,99.83 261,99.77 261,95.69 260.99,95.63 260.96,95.59 256.5,91.13 256.5,88.53 256.46,88.42 256.35,88.38
SIG115 on BOTTOM: 246.07,85 246.01,85.01 245.97,85.04 245.05,85.96 245.02,86 245.01,86.06 245.01,98.98 245.02,99.04 245.05,99.08 245.75,99.78 245.8,99.81 245.86,99.83 251.37,99.83 253.89,102.35 253.93,102.38 253.99,102.39 258.35,102.39 258.41,102.38 258.45,102.35 261.06,99.74 261.09,99.7 261.1,99.64 261.1,91.8 262.76,90.14 262.79,90.1 262.8,90.04 262.8,85.15 262.76,85.04 262.65,85
SIG116 on BOTTOM: 266.56,69.09 266.5,69.1 266.45,69.13 265.37,70.21 265.32,70.29 265.3,70.39 265.3,71.94 264.2,73.04 263.04,73.04 262.95,73.06 262.86,73.11 259.83,76.15 248.04,76.15 247.21,75.86 247.11,75.85 246.75,75.85 246.2,76.4 246.75,76.95 247.11,76.95 247.21,76.94 248.04,76.65 259.93,76.65 260.02,76.63 260.11,76.58 263.14,73.54 264.3,73.54 264.4,73.52 265.73,72.22 265.78,72.14 265.8,72.04 265.8,70.49 266.65,69.64 268.2,69.64 268.31,69.6 268.35,69.49 268.35,69.24 268.31,69.13 268.2,69.09
SIG117 on BOTTOM: 268.31,71.58 268.11,71.63 267.95,71.78 267.64,72.3 266.62,73.32 266.48,73.46 266.45,73.51 266.44,73.57 266.44,73.64 266.2,74.3 265.68,74.3 265.1,74.16 265.01,74.15 264.7,74.15 264.3,74.55 264.7,74.95 265.01,74.95 265.05,74.95 265.1,74.94 265.68,74.8 266.07,74.8 266.25,74.98 266.25,75.16 266.81,75.7 267.35,75.15 267.35,74.7 267.34,74.61 267.05,73.78 267.05,73.6 268,72.66 268.42,72.41 268.79,72.41 268.84,72.4 269.48,72.24 269.64,72.24 270.22,72.83 270.3,72.88 270.4,72.9 271.2,72.9 271.32,73.02 271.6,73.08 271.75,72.85 271.75,72.43 271.68,72.25 271.5,72.18 271.42,72.18 271.33,72.2 271.25,72.25 271.1,72.4 270.5,72.4 269.92,71.82 269.89,71.79 269.85,71.77 269.8,71.75 269.74,71.74 269.48,71.74 268.84,71.58 268.79,71.58
SIG124 on BOTTOM: 258.3,121.1 257.93,121.47 257.33,121.29 257.26,121.29 256.18,121.29 256.07,121.3 255.98,121.34 255.69,121.47 255.41,121.34 255.31,121.3 255.21,121.29 254.65,121.29 254.6,121.29 254.55,121.29 254.16,121.29 254.09,121.29 254.03,121.31 253.39,121.5 252.68,121.5 252.62,121.51 252.58,121.54 252.54,121.58 252.51,121.62 252.5,121.68 252.5,122.1 252.54,122.21 252.65,122.25 252.93,122.25 252.98,122.24 253.03,122.21 254.55,122.21 254.6,122.21 254.65,122.21 255.21,122.21 255.26,122.21 255.3,122.2 256.08,122.2 256.13,122.21 256.18,122.21 257.26,122.21 257.33,122.21 257.39,122.19 258.07,121.99 258.13,121.96 258.18,121.93 258.72,121.39 258.72,121.38 258.78,121.3 258.8,121.2 258.8,119.97 258.55,119.72 258.3,119.97
SIG126 on BOTTOM: 265.78,117.54 265.68,117.56 265.6,117.61 264.47,118.77 264.45,118.87 264.45,119.82 262.39,121.88 260.16,121.88 260.07,121.9 258.64,123.3 247.96,123.3 247.13,123.01 247.04,123 246.79,123 246.18,122.72 246.13,122.71 246.07,122.7 245.37,122.7 244.79,122.56 244.74,122.55 244.7,122.55 244.53,122.55 244.48,122.55 244.43,122.56 243.86,122.7 242.77,122.7 242.67,122.72 240.85,124.51 240.82,124.56 240.81,124.62 240.81,126.71 240.85,126.82 240.96,126.86 241.23,126.86 241.34,126.82 241.38,126.71 241.38,124.69 242.87,123.2 243.86,123.2 244.48,123.35 244.53,123.35 244.7,123.35 244.74,123.35 244.79,123.34 245.37,123.2 245.91,123.2 246.17,123.78 246.38,124.01 246.68,124.1 247.04,124.1 247.13,124.09 247.96,123.8 258.74,123.8 258.83,123.78 258.92,123.73 260.26,122.38 262.49,122.38 262.58,122.36 262.67,122.31 264.88,120.1 264.93,120.02 264.95,119.92 264.95,118.97 265.89,118.03 266.08,117.76 265.83,117.54
SIG127 on BOTTOM: 269.58,119.6 269.52,119.61 269.48,119.64 269.35,119.77 268.24,119.77 268.14,119.79 268.06,119.84 267.69,120.22 267.14,120.08 267.09,120.08 266.61,120.08 266.32,120.2 266.19,120.49 266.19,120.8 266.2,120.85 266.35,121.47 266.35,121.51 266.09,122.22 265.4,122.22 264.78,122.07 264.73,122.07 264.43,122.07 264.02,122.47 264.43,122.87 264.73,122.87 264.78,122.87 264.82,122.86 265.4,122.72 265.75,122.72 266.05,123.02 266.05,123.09 266.61,123.62 267.15,123.07 267.15,122.44 267.14,122.34 266.86,121.53 266.86,121.49 267.01,120.91 267.09,120.91 267.14,120.9 267.79,120.74 267.87,120.72 267.94,120.67 268.34,120.27 269.35,120.27 269.67,120.59 269.71,120.62 269.77,120.63 270.03,120.63 270.14,120.59 270.18,120.48 270.18,119.75 270.14,119.64 270.03,119.6
SIG134 on TOP: 254.07,139.13 254.01,139.14 253.97,139.17 252.37,140.77 252.34,140.81 252.33,140.87 252.33,146.48 252.34,146.54 252.37,146.58 253.43,147.64 253.47,147.67 253.53,147.68 258.54,147.68 258.6,147.67 258.64,147.64 259.7,146.58 259.73,146.54 259.74,146.48 259.74,140.6 259.73,140.54 259.7,140.5 258.37,139.17 258.33,139.14 258.27,139.13
SIG134 on BOTTOM: 246.15,132.3 246.04,132.34 246,132.45 246,140.24 246.01,140.3 246.04,140.34 246.76,141.06 246.8,141.09 246.86,141.1 248.5,141.1 250.7,143.3 250.7,146.74 250.71,146.8 250.74,146.84 252.86,148.96 252.9,148.99 252.96,149 259.74,149 259.8,148.99 259.84,148.96 260.86,147.94 260.89,147.9 260.9,147.84 260.9,139.1 262.46,137.54 262.49,137.5 262.5,137.44 262.5,132.45 262.46,132.34 262.35,132.3
SIG135 on TOP: 265.33,139.13 265.27,139.14 265.23,139.17 263.83,140.57 263.8,140.61 263.79,140.67 263.79,146.43 263.8,146.49 263.83,146.53 264.96,147.66 265,147.69 265.06,147.7 269.97,147.7 270.03,147.69 270.07,147.66 271.2,146.53 271.23,146.49 271.24,146.43 271.24,140.35 271.23,140.29 271.2,140.25 270.12,139.17 270.08,139.14 270.02,139.13
SIG135 on BOTTOM: 265.15,132.2 265.04,132.24 265,132.35 265,137.2 262.54,139.66 262.51,139.7 262.5,139.76 262.5,147.74 262.51,147.8 262.54,147.84 263.66,148.96 263.7,148.99 263.76,149 271.24,149 271.3,148.99 271.34,148.96 272.56,147.74 272.59,147.7 272.6,147.64 272.6,141.33 273.8,140.13 276.44,140.13 276.5,140.12 276.54,140.09 277.63,139 280.85,139 280.96,138.96 281,138.85 281,132.35 280.96,132.24 280.85,132.2
SIG136 on TOP: 272.1,37.15 271.99,37.19 271.95,37.3 271.95,39.5 271.75,39.7 270.33,39.7 270.22,39.74 270.18,39.85 270.18,41.35 270.22,41.46 270.33,41.5 278.6,41.5 278.66,41.56 278.7,41.59 278.76,41.6 278.99,41.6 279.1,41.56 279.14,41.45 279.14,40.7 279.1,40.59 278.99,40.55 278.1,40.55 277.89,40.34 277.85,40.31 277.79,40.3 276.1,40.3 275.65,39.85 275.65,37.3 275.61,37.19 275.5,37.15
SIG183 on BOTTOM: 258.88,9.72 258.84,9.73 258.54,9.78 256.18,9.78 256.12,9.79 256.07,9.82 255.97,9.92 255.94,9.97 255.93,10.03 255.93,10.35 255.86,10.67 255.85,10.79 255.83,10.84 255.82,10.9 255.82,11.5 255.6,11.72 254.8,11.72 254.55,11.97 254.8,12.22 255.97,12.22 256.21,12.21 256.32,12 256.32,10.9 256.32,10.84 256.3,10.79 256.29,10.67 256.23,10.35 256.23,10.09 256.24,10.07 258.54,10.07 258.84,10.12 258.88,10.12 259.64,10.12 259.84,9.93 259.64,9.72
SIG193 on TOP: 24.29,34.27 24.23,34.29 24.18,34.32 18.3,40.2 10.99,40.2 10.93,40.21 10.89,40.24 9.16,41.97 9.13,42.01 9.12,42.07 9.12,44.08 9.13,44.14 9.16,44.18 10.09,45.11 10.13,45.14 10.19,45.15 10.64,45.15 10.67,45.16 10.7,45.17 12.85,45.56 16.67,49.38 16.67,58.43 13.69,61.41 12.96,61.41 11.95,60.65 11.95,60.65 11.74,60.68 11.77,60.89 12.37,61.34 12.37,62.5 11.77,62.95 11.74,63.16 11.95,63.19 11.95,63.19 13.48,62.04 13.5,62.03 16.96,58.55 16.97,58.49 16.97,49.32 16.96,49.26 14.11,46.4 14.11,45.6 14.56,45.15 29.55,45.15 29.61,45.14 29.65,45.11 30.5,44.26 30.53,44.22 30.54,44.16 30.54,38.75 30.53,38.69 30.5,38.65 26.17,34.32 26.12,34.29 26.06,34.27
SIG199 on CONDUCTIVE3 (solid shape): 59.24,52.89 59.51,53.08 59.74,52.83 59.73,52.78 59.63,52.32 60.82,51.13 61.28,51.23 61.58,51.04 61.39,50.74 60.8,50.61 59.02,50.22 58.79,50.29 58.72,50.52
SIG199 on TOP, BOTTOM, CONDUCTIVE2, CONDUCTIVE5: 44.26,50.7 44.2,50.71 44.16,50.74 43.54,51.36 43.51,51.4 43.5,51.46 43.5,68.59 43.51,68.65 43.54,68.69 44.61,69.76 44.65,69.79 44.71,69.8 47.39,69.8 47.45,69.79 47.49,69.76 48.46,68.79 48.49,68.75 48.5,68.69 48.5,51.66 48.49,51.6 48.46,51.56 47.64,50.74 47.6,50.71 47.54,50.7
SIG199 on TOP, BOTTOM, CONDUCTIVE2, CONDUCTIVE5: 59.26,50.75 59.2,50.76 59.16,50.79 58.54,51.41 58.51,51.45 58.5,51.51 58.5,68.64 58.51,68.7 58.54,68.74 59.76,69.96 59.8,69.99 59.86,70 62.19,70 62.25,69.99 62.29,69.96 63.46,68.79 63.49,68.75 63.5,68.69 63.5,51.66 63.49,51.6 63.46,51.56 62.69,50.79 62.65,50.76 62.59,50.75
SIG00516 on TOP: 266.66,88.39 266.6,88.4 266.55,88.44 262.54,92.45 262.51,92.49 262.5,92.55 262.5,99.48 262.51,99.54 262.54,99.58 265.35,102.39 265.39,102.42 265.45,102.43 270.57,102.43 270.63,102.42 270.67,102.39 272.63,100.43 272.66,100.39 272.67,100.33 272.67,95.51 272.66,95.45 272.63,95.41 267.96,90.74 267.96,88.54 267.92,88.43 267.81,88.39
SIG00516 on BOTTOM: 264.75,85.01 264.64,85.05 264.6,85.16 264.6,90.49 262.56,92.53 262.53,92.57 262.52,92.63 262.52,99.49 262.53,99.55 262.56,99.59 265.38,102.41 265.42,102.44 265.48,102.45 270.59,102.45 270.65,102.44 270.69,102.41 274.06,99.04 278.56,99.04 278.62,99.03 278.66,99 280.54,97.12 280.57,97.08 280.58,97.02 280.58,85.16 280.54,85.05 280.43,85.01
SIG00791 on TOP: 110.3,1.55 110.19,1.59 110.15,1.7 110.15,3.45 110.19,3.56 110.3,3.6 112.29,3.6 112.35,3.59 112.39,3.56 112.85,3.1 112.88,3.06 112.89,3 112.89,1.91 112.88,1.85 112.85,1.81 112.63,1.59 112.59,1.56 112.53,1.55
SIG00799 on TOP: 239.01,1.56 238.96,1.57 238.87,1.65 238.87,1.76 238.88,1.78 238.67,1.85 238.74,2.05 239.13,2.24 240.1,3.22 240.1,10.15 240.11,10.21 242.24,12.36 242.29,12.39 242.35,12.4 258.98,12.4 259.03,12.39 259.08,12.36 260.12,11.32 260.4,11.14 260.43,11.11 260.45,11.08 260.46,10.97 260.4,10.89 260.36,10.87 260.34,10.83 260.23,10.76 260.11,10.8 260.09,10.83 259.9,11.11 258.91,12.1 242.41,12.1 240.4,10.09 240.4,3.15 240.39,3.1 240.36,3.05 239.6,2.29 239.6,1.71 239.56,1.61 239.45,1.56
SIG007127 on TOP: 225.22,3.4 225.18,3.5 225.18,3.55 225.21,3.6 225.18,3.65 225.18,3.7 225.22,3.8 225.32,3.85 225.36,3.84 225.72,3.75 225.88,3.75 226.69,4.56 226.69,5.65 227.15,6.11 227.61,5.65 227.61,4.8 227.94,4.47 228.59,4.47 229.05,4.62 229.09,4.62 229.72,4.62 230.03,4.32 229.72,4.02 229.09,4.02 229.05,4.02 228.59,4.17 227.7,4.17 227.66,4.18 227.62,4.2 227.59,4.21 227.36,4.44 227,4.44 226.05,3.49 226,3.46 225.94,3.45 225.72,3.45 225.36,3.36 225.32,3.35
SIG008104 on BOTTOM: 204.15,3.38 203.87,3.41 203.6,3.52 202.28,4.25 201.31,4.25 201.2,4.14 201.16,4.11 201.1,4.1 200.94,4.1 200.88,4.11 200.84,4.14 200.76,4.22 198.54,4.22 198.43,4.26 198.39,4.37 198.39,4.65 198.43,4.76 198.54,4.8 200.77,4.8 200.79,4.82 200.83,4.85 200.89,4.86 201.14,4.86 201.2,4.85 201.24,4.82 201.31,4.75 201.99,4.75 202.23,4.99 202.31,5.04 202.4,5.06 202.84,5.06 203.87,5.59 204.15,5.62 205.3,5.62 205.58,5.59 205.85,5.48 207.17,4.75 208.47,4.75 209.23,4.99 209.31,5 210.95,5 211.04,4.98 211.12,4.93 211.79,4.26 212.11,4.26 213.01,4.6 213.12,4.61 213.5,4.61 214.1,4.01 213.5,3.41 213.12,3.41 213.01,3.42 212.9,3.45 212.11,3.76 210.77,3.76 210.67,3.78 210.59,3.83 210.4,4.02 210.34,4 210.28,4 209.31,4 209.23,4.01 209.15,4.02 208.47,4.25 207.17,4.25 205.85,3.52 205.58,3.41 205.3,3.38
SIG008104 on BOTTOM: 202.36,5.6 202.33,5.72 202.4,6.05 202.4,6.19 202.19,6.4 201.5,6.4 201.2,6.35 201.17,6.35 201,6.35 200.8,6.55 201,6.75 201.17,6.75 201.2,6.75 201.5,6.7 201.59,6.7 201.69,6.8 201.69,6.89 201.32,7.27 201.29,7.32 201.28,7.38 201.28,7.45 201.21,7.77 201.2,7.82 201.2,8 201.43,8.22 201.65,8 201.65,7.82 201.64,7.77 201.57,7.45 201.57,7.44 202.31,6.7 202.69,6.7 202.89,6.91 202.94,6.94 203,6.95 208.53,6.95 209.15,7.25 209.26,7.29 209.37,7.3 210.28,7.3 210.78,6.8 210.28,6.3 209.37,6.3 209.26,6.31 209.15,6.35 208.53,6.65 203.06,6.65 202.7,6.29 202.7,6.05 202.77,5.72 202.74,5.6 202.62,5.54 202.59,5.55 202.55,5.56 202.51,5.55 202.48,5.54
SIG008106 on BOTTOM: 244.99,12.07 244.93,12.09 244.88,12.12 244.8,12.2 244.5,12.2 244.39,12.24 244.34,12.35 244.34,12.5 244.41,12.66 244.57,12.72 244.75,12.72 244.8,12.72 245.12,12.65 246.18,12.65 246.77,12.89 246.85,12.9 247.47,12.9 247.88,12.49 247.47,12.07
SIG008107 on BOTTOM: 249.78,9.9 249.36,10.31 249.78,10.72 250.36,10.72 250.44,10.72 250.53,10.69 251.05,10.46 252.15,10.46 253.05,11.36 253.05,12.14 252.85,12.34 251.8,12.34 251.61,12.14 251.56,12.11 251.5,12.1 250.53,12.1 250.46,12.08 250.39,12.07 249.78,12.07 249.36,12.49 249.78,12.9 250.39,12.9 250.47,12.89 250.56,12.87 251.08,12.64 252.85,12.64 253.05,12.84 253.05,13.33 252.93,13.45 252.9,13.49 252.89,13.55 252.89,13.85 252.93,13.96 253.04,14 253.33,14 253.44,13.96 253.48,13.85 253.48,13.55 253.47,13.49 253.44,13.45 253.35,13.36 253.35,11.3 253.34,11.24 252.32,10.21 252.27,10.17 252.21,10.16 251.05,10.16 250.53,9.93 250.44,9.91 250.36,9.9
SIG008111 on TOP: 220.73,34.32 220.67,34.33 219.53,34.6 208.69,34.6 208.58,34.64 208.54,34.75 208.54,38.24 208.55,38.3 208.58,38.34 209.11,38.87 209.15,38.9 209.21,38.91 210.23,38.91 210.29,38.9 210.33,38.87 213.6,35.6 219.53,35.6 220.67,35.87 220.78,35.88 221.18,35.69 221.27,35.26 221.24,35.18 221.2,35.1 221.24,35.02 221.27,34.94 221.18,34.51 220.78,34.32
SIG008111 on TOP: 209.08,26.26 209.02,26.27 208.98,26.3 208.59,26.69 208.56,26.73 208.55,26.79 208.55,31.67 208.56,31.73 208.59,31.77 209.59,32.77 209.63,32.8 209.69,32.81 216.64,32.81 216.75,32.77 216.79,32.66 216.79,31.7 216.75,31.59 216.64,31.55 214.58,31.55 213.5,30.47 213.5,26.41 213.46,26.3 213.35,26.26
SIG008112 on BOTTOM (solid shape): 212.84,22.32 213.43,22.23 213.52,21.64 212.84,20.36 212.22,20.12 211.91,20.71 211.32,21.02 211.56,21.64
SIG008112 on TOP: 219.95,26.64 219.89,26.65 219.85,26.68 219.73,26.8 215.44,26.8 215.33,26.84 215.29,26.95 215.29,27.86 215.33,27.97 215.44,28.01 219.56,28.01 219.82,28.27 219.86,28.3 219.92,28.31 221.27,28.31 221.33,28.3 221.37,28.27 221.64,28 221.67,27.96 221.68,27.9 221.68,27.11 221.67,27.05 221.64,27.01 221.31,26.68 221.27,26.65 221.21,26.64
SIG008113 on TOP: 202.49,15.29 202.44,15.3 202.29,15.44 202.29,15.64 202.29,17.75 202.33,17.86 202.44,17.9 204.75,17.9 205.28,18.44 205.34,18.48 205.41,18.5 206.57,19.11 206.9,18.99 206.79,18.66 206.3,18.4 206.3,18.12 206.79,17.86 206.84,17.83 206.88,17.79 206.87,17.48 206.57,17.41 205.83,17.79 205.35,17.79 203.27,15.71 202.91,15.13 202.64,15.09 202.5,15.24
SIG008113 on TOP: 203.05,12.03 202.99,12.04 202.95,12.07 201.95,13.07 201.92,13.11 201.91,13.17 201.91,14.07 201.95,14.18 202.06,14.22 204.72,14.22 204.83,14.18 204.87,14.07 204.87,12.18 204.83,12.07 204.72,12.03
SIG008113 on TOP: 202.42,10.93 202.41,10.94 197.94,10.94 197.88,10.95 197.83,10.98 197.49,11.32 197.48,11.34 197.46,11.37 197.31,11.69 195.1,11.69 194.64,12.15 195.1,12.61 196.68,12.61 197.1,13.03 197.1,16.2 197.14,16.39 197.25,16.55 202.25,21.55 204.55,23.8 204.74,23.84 205.4,23.84 206.72,24.25 206.79,24.26 206.87,24.27 207.31,24.01 207.28,23.49 207.21,23.41 207.12,23.34 207.21,23.27 207.28,23.19 207.31,22.67 206.87,22.41 206.79,22.42 206.72,22.43 205.4,22.84 204.95,22.84 203.31,21.2 203.01,20.91 202.75,20.37 202.75,19.08 202.82,18.75 202.82,18.7 202.82,18.52 202.6,18.3 202.38,18.52 202.38,18.7 202.38,18.75 202.45,19.08 202.45,19.82 202.32,19.95 202.06,19.95 198.1,15.99 198.1,13.02 198.51,12.61 200.1,12.61 200.56,12.15 200.1,11.69 197.89,11.69 197.81,11.53 197.81,11.43 198,11.24 202.47,11.24 202.53,11.23 202.63,11.14 202.98,10.95 203.05,10.78 202.91,10.67 202.89,10.67 202.89,10.65 202.78,10.51 202.61,10.58
SIG008113 on BOTTOM: 206.65,9.64 206.66,9.69 206.72,10.02 206.72,10.45 206.57,10.6 206.45,10.66 206.4,10.66 206.33,10.59 206.33,10.5 206.41,10.23 206.42,10.16 206.39,10.1 206.34,10.05 206.27,10.04 206.2,10.05 206.15,10.1 206.1,10.05 206.03,10.04 205.99,10.04 205.9,10.11 205.89,10.23 205.97,10.5 205.97,10.61 205.8,10.77 205.77,10.78 205.74,10.79 205.32,10.94 205.05,10.88 205,10.88 204.82,10.88 204.6,11.1 204.82,11.32 205,11.32 205.05,11.32 205.34,11.26 205.74,11.4 205.79,11.42 205.85,11.42 206.95,11.42 207.06,11.38 207.1,11.27 207.1,10.44 207.09,10.38 207.06,10.33 207.03,10.3 207.03,10.02 207.09,9.69 207.1,9.64 207.1,9.5 206.88,9.28 206.65,9.5
SIG008116 on BOTTOM: 221.04,18.08 221.05,18.23 221.07,18.26 221.1,18.28 221.48,18.5 221.48,18.9 221.1,19.12 221.09,19.12 221.05,19.33 221.25,19.38 222.15,18.85 222.56,18.85 222.63,18.92 222.81,19.2 222.83,19.22 222.95,19.27 223.06,19.2 223.08,19.16 223.11,19.15 223.19,19.05 223.17,18.93 223.15,18.91 223.12,18.89 222.84,18.7 222.73,18.59 222.69,18.57 222.66,18.55 222.62,18.55 222.15,18.55 221.25,18.02 221.21,18.01 221.17,18
SIG008121 on TOP: 240.26,28.84 240.15,28.88 240.11,28.99 240.11,36.6 240.12,36.66 240.15,36.7 241.95,38.5 241.99,38.53 242.05,38.54 248.63,38.54 248.74,38.5 248.78,38.39 248.78,32.63 248.77,32.57 248.74,32.53 245.09,28.88 245.05,28.85 244.99,28.84
SIG008125 on BOTTOM: 198.85,0.9 198.79,0.91 198.74,0.94 197.33,2.36 197.3,2.4 197.29,2.46 197.29,2.5 197.33,2.61 197.44,2.65 197.63,2.65 197.74,2.61 197.78,2.5 197.78,2.33 198.91,1.2 216.53,1.2 219.03,3.7 219.03,3.88 218.88,4.03 217.43,4.03 217.37,4.04 217.32,4.07 217.06,4.34 217.02,4.39 217.01,4.45 217.01,5.82 216.78,6.34 216.76,6.43 216.75,6.51 216.75,7.12 217.16,7.54 217.57,7.12 217.57,6.51 217.57,6.43 217.54,6.34 217.31,5.82 217.31,4.51 217.49,4.33 218.88,4.33 219.03,4.48 219.03,4.65 218.96,4.97 218.95,5.02 218.95,5.48 218.96,5.54 218.99,5.59 219.19,5.78 219.19,6.07 218.96,6.59 218.93,6.67 218.93,6.76 218.93,7.12 219.34,7.54 219.75,7.12 219.75,6.76 219.74,6.67 219.72,6.59 219.49,6.07 219.49,5.53 219.48,5.47 219.44,5.43 219.4,5.38 219.4,5.02 219.39,4.97 219.32,4.65 219.32,3.63 219.31,3.58 216.7,0.94 216.65,0.91 216.59,0.9
